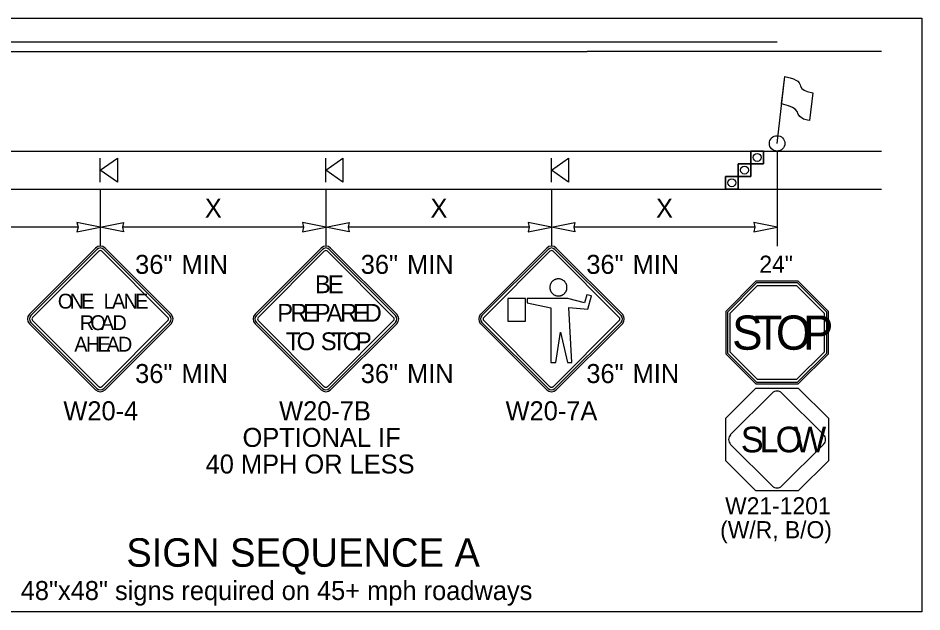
# Model space of a CAD drawing. Extents: x 99999.1 to 100095.7, y 99995 to 100010.7.
# Drawn here: x 100021.344 to 100025.15, y 100006.18 to 100008.68 of the extents above; entities that cross this region are included whole.
import ezdxf

# ---------------------------------------------------------------- set-up
doc = ezdxf.new("R2010")
doc.units = 0
for name, color, linetype in [('RD_ED_ShoulderPavedEdge', 7, 'Continuous'), ('RD_MK_LineDblYellowCenter', 7, 'Continuous'), ('RD_MK_LineEdgeWhite', 7, 'Continuous'), ('RD_MK_LineNoPass', 7, 'Continuous'), ('RD_MK_LineSkipCenter', 7, 'Continuous'), ('SH_DE_DetailHeading2Text', 7, 'Continuous'), ('TR_SN_ConstructionSigns', 7, 'Continuous'), ('TR_WZ_FlaggingStation', 7, 'Continuous'), ('TR_WZ_PortableSignMountBlk-Org', 7, 'Continuous'), ('TR_WZ_TrafficCone', 7, 'Continuous'), ('TR_WZ_WorkZoneDetails', 7, 'Continuous'), ('TR_WZ_WorkZoneTextCurrent', 7, 'Continuous')]:
    doc.layers.add(name, color=color, linetype=linetype)

msp = doc.modelspace()

# ---------------------------------------------------------------- linework, layer by layer
at = {"layer": 'RD_ED_ShoulderPavedEdge'}
msp.add_line((100020.3, 100007.9602), (100024.9804, 100007.9602), dxfattribs=at)
at = {"layer": 'RD_MK_LineDblYellowCenter'}
for p, q in [((100020.3, 100008.5802), (100023.7402, 100008.5802)), ((100020.3, 100008.5402), (100023.7402, 100008.5402))]:
    msp.add_line(p, q, dxfattribs=at)
at = {"layer": 'RD_MK_LineEdgeWhite'}
msp.add_line((100020.3, 100008.1202), (100024.9804, 100008.1202), dxfattribs=at)
at = {"layer": 'RD_MK_LineNoPass'}
msp.add_line((100023.7402, 100008.5802), (100024.5402, 100008.5802), dxfattribs=at)
at = {"layer": 'RD_MK_LineSkipCenter'}
msp.add_lwpolyline([(100024.9804, 100008.5402), (100023.7402, 100008.5402)], dxfattribs=at)
at = {"layer": 'TR_SN_ConstructionSigns'}
for p, q in [((100021.6703, 100007.712), (100021.3919, 100007.4336)), ((100021.6758, 100007.7065), (100021.3974, 100007.428)), ((100021.4051, 100007.4203), (100021.6835, 100007.6987)), ((100021.6968, 100007.6987), (100021.9752, 100007.4203)), ((100021.9829, 100007.428), (100021.7045, 100007.7065)), ((100021.9885, 100007.4336), (100021.71, 100007.712)), ((100022.6203, 100007.712), (100022.3419, 100007.4336)), ((100022.6258, 100007.7065), (100022.3474, 100007.428)), ((100022.3551, 100007.4203), (100022.6335, 100007.6987)), ((100022.6468, 100007.6987), (100022.9252, 100007.4203)), ((100022.9329, 100007.428), (100022.6545, 100007.7065)), ((100022.9385, 100007.4336), (100022.66, 100007.712)), ((100023.5703, 100007.712), (100023.2919, 100007.4336)), ((100023.5758, 100007.7065), (100023.2974, 100007.428)), ((100023.3051, 100007.4203), (100023.5835, 100007.6987)), ((100023.5968, 100007.6987), (100023.8752, 100007.4203)), ((100023.8829, 100007.428), (100023.6045, 100007.7065)), ((100023.8885, 100007.4336), (100023.61, 100007.712)), ((100023.5956, 100007.5735), (100023.5942, 100007.5722)), ((100023.5971, 100007.5747), (100023.5956, 100007.5735)), ((100023.5986, 100007.5759), (100023.5971, 100007.5747)), ((100023.6002, 100007.5769), (100023.5986, 100007.5759)), ((100023.6019, 100007.5779), (100023.6002, 100007.5769)), ((100023.6036, 100007.5788), (100023.6019, 100007.5779)), ((100023.6053, 100007.5796), (100023.6036, 100007.5788)), ((100023.6071, 100007.5803), (100023.6053, 100007.5796)), ((100023.6089, 100007.5809), (100023.6071, 100007.5803)), ((100023.6108, 100007.5814), (100023.6089, 100007.5809)), ((100023.6127, 100007.5818), (100023.6108, 100007.5814)), ((100023.6146, 100007.5821), (100023.6127, 100007.5818)), ((100023.6164, 100007.5823), (100023.6146, 100007.5821)), ((100023.6184, 100007.5824), (100023.6164, 100007.5823)), ((100023.6203, 100007.5824), (100023.6184, 100007.5824)), ((100023.6222, 100007.5823), (100023.6203, 100007.5824)), ((100023.6241, 100007.5821), (100023.6222, 100007.5823)), ((100023.626, 100007.5818), (100023.6241, 100007.5821)), ((100023.6279, 100007.5814), (100023.626, 100007.5818)), ((100023.6297, 100007.5809), (100023.6279, 100007.5814)), ((100023.6316, 100007.5803), (100023.6297, 100007.5809)), ((100023.6333, 100007.5796), (100023.6316, 100007.5803)), ((100023.6351, 100007.5788), (100023.6333, 100007.5796)), ((100023.6368, 100007.5779), (100023.6351, 100007.5788)), ((100023.6385, 100007.5769), (100023.6368, 100007.5779)), ((100023.64, 100007.5759), (100023.6385, 100007.5769)), ((100023.6416, 100007.5747), (100023.64, 100007.5759)), ((100023.643, 100007.5735), (100023.6416, 100007.5747)), ((100023.6445, 100007.5722), (100023.643, 100007.5735)), ((100023.5835, 100007.5502), (100023.5833, 100007.5483)), ((100023.5833, 100007.5483), (100023.5833, 100007.5464)), ((100023.5833, 100007.5464), (100023.5833, 100007.5445)), ((100023.5833, 100007.5445), (100023.5835, 100007.5426)), ((100023.5838, 100007.5522), (100023.5835, 100007.5502)), ((100023.5835, 100007.5426), (100023.5838, 100007.5407)), ((100023.5842, 100007.554), (100023.5838, 100007.5522)), ((100023.5838, 100007.5407), (100023.5842, 100007.5388)), ((100023.5846, 100007.5559), (100023.5842, 100007.554)), ((100023.5842, 100007.5388), (100023.5846, 100007.5369)), ((100023.5852, 100007.5577), (100023.5846, 100007.5559)), ((100023.5846, 100007.5369), (100023.5852, 100007.5351)), ((100023.5858, 100007.5595), (100023.5852, 100007.5577)), ((100023.5852, 100007.5351), (100023.5858, 100007.5333)), ((100023.5865, 100007.5613), (100023.5858, 100007.5595)), ((100023.5873, 100007.563), (100023.5865, 100007.5613)), ((100023.5883, 100007.5647), (100023.5873, 100007.563)), ((100023.5894, 100007.5664), (100023.5883, 100007.5647)), ((100023.5904, 100007.5679), (100023.5894, 100007.5664)), ((100023.5916, 100007.5694), (100023.5904, 100007.5679)), ((100023.5929, 100007.5709), (100023.5916, 100007.5694)), ((100023.5942, 100007.5722), (100023.5929, 100007.5709)), ((100023.6458, 100007.5709), (100023.6445, 100007.5722)), ((100023.647, 100007.5694), (100023.6458, 100007.5709)), ((100023.6482, 100007.5679), (100023.647, 100007.5694)), ((100023.6494, 100007.5664), (100023.6482, 100007.5679)), ((100023.6504, 100007.5647), (100023.6494, 100007.5664)), ((100023.6513, 100007.563), (100023.6504, 100007.5647)), ((100023.6521, 100007.5613), (100023.6513, 100007.563)), ((100023.6529, 100007.5595), (100023.6521, 100007.5613)), ((100023.6535, 100007.5577), (100023.6529, 100007.5595)), ((100023.6529, 100007.5333), (100023.6535, 100007.5351)), ((100023.6541, 100007.5559), (100023.6535, 100007.5577)), ((100023.6535, 100007.5351), (100023.6541, 100007.5369)), ((100023.6545, 100007.554), (100023.6541, 100007.5559)), ((100023.6541, 100007.5369), (100023.6545, 100007.5388)), ((100023.6549, 100007.5522), (100023.6545, 100007.554)), ((100023.6545, 100007.5388), (100023.6549, 100007.5407)), ((100023.6552, 100007.5502), (100023.6549, 100007.5522)), ((100023.6549, 100007.5407), (100023.6552, 100007.5426)), ((100023.6553, 100007.5483), (100023.6552, 100007.5502)), ((100023.6552, 100007.5426), (100023.6553, 100007.5445)), ((100023.6554, 100007.5464), (100023.6553, 100007.5483)), ((100023.6553, 100007.5445), (100023.6554, 100007.5464)), ((100024.4506, 100007.5722), (100024.3241, 100007.4457)), ((100024.4534, 100007.5655), (100024.3308, 100007.4429)), ((100024.3421, 100007.4383), (100024.4581, 100007.5542)), ((100024.6295, 100007.5722), (100024.4506, 100007.5722)), ((100024.6267, 100007.5655), (100024.4534, 100007.5655)), ((100024.4581, 100007.5542), (100024.6221, 100007.5542)), ((100024.6221, 100007.5542), (100024.7381, 100007.4383)), ((100024.7493, 100007.4429), (100024.6267, 100007.5655)), ((100024.7561, 100007.4457), (100024.6295, 100007.5722)), ((100023.4059, 100007.4991), (100023.4059, 100007.4044)), ((100023.4812, 100007.4991), (100023.4059, 100007.4991)), ((100023.4812, 100007.4044), (100023.4812, 100007.4991)), ((100023.6596, 100007.4991), (100023.4882, 100007.4991)), ((100023.4882, 100007.4991), (100023.4882, 100007.481)), ((100023.5858, 100007.5333), (100023.5865, 100007.5315)), ((100023.5865, 100007.5315), (100023.5873, 100007.5298)), ((100023.5873, 100007.5298), (100023.5883, 100007.5281)), ((100023.5883, 100007.5281), (100023.5894, 100007.5265)), ((100023.5894, 100007.5265), (100023.5904, 100007.5249)), ((100023.5904, 100007.5249), (100023.5916, 100007.5234)), ((100023.5916, 100007.5234), (100023.5929, 100007.522)), ((100023.5929, 100007.522), (100023.5942, 100007.5206)), ((100023.5942, 100007.5206), (100023.5956, 100007.5193)), ((100023.5956, 100007.5193), (100023.5971, 100007.5181)), ((100023.5971, 100007.5181), (100023.5986, 100007.5169)), ((100023.5986, 100007.5169), (100023.6002, 100007.5159)), ((100023.6002, 100007.5159), (100023.6019, 100007.5149)), ((100023.6019, 100007.5149), (100023.6036, 100007.514)), ((100023.6036, 100007.514), (100023.6053, 100007.5132)), ((100023.6053, 100007.5132), (100023.6071, 100007.5125)), ((100023.6071, 100007.5125), (100023.6089, 100007.5119)), ((100023.6089, 100007.5119), (100023.6108, 100007.5114)), ((100023.6108, 100007.5114), (100023.6127, 100007.511)), ((100023.6127, 100007.511), (100023.6146, 100007.5107)), ((100023.6146, 100007.5107), (100023.6164, 100007.5105)), ((100023.6164, 100007.5105), (100023.6184, 100007.5104)), ((100023.6184, 100007.5104), (100023.6203, 100007.5104)), ((100023.6203, 100007.5104), (100023.6222, 100007.5105)), ((100023.6222, 100007.5105), (100023.6241, 100007.5107)), ((100023.6241, 100007.5107), (100023.626, 100007.511)), ((100023.626, 100007.511), (100023.6279, 100007.5114)), ((100023.6279, 100007.5114), (100023.6297, 100007.5119)), ((100023.6297, 100007.5119), (100023.6316, 100007.5125)), ((100023.6316, 100007.5125), (100023.6333, 100007.5132)), ((100023.6333, 100007.5132), (100023.6351, 100007.514)), ((100023.6351, 100007.514), (100023.6368, 100007.5149)), ((100023.6368, 100007.5149), (100023.6385, 100007.5159)), ((100023.6385, 100007.5159), (100023.64, 100007.5169)), ((100023.64, 100007.5169), (100023.6416, 100007.5181)), ((100023.6416, 100007.5181), (100023.643, 100007.5193)), ((100023.643, 100007.5193), (100023.6445, 100007.5206)), ((100023.6445, 100007.5206), (100023.6458, 100007.522)), ((100023.6458, 100007.522), (100023.647, 100007.5234)), ((100023.647, 100007.5234), (100023.6482, 100007.5249)), ((100023.6482, 100007.5249), (100023.6494, 100007.5265)), ((100023.6494, 100007.5265), (100023.6504, 100007.5281)), ((100023.6504, 100007.5281), (100023.6513, 100007.5298)), ((100023.6513, 100007.5298), (100023.6521, 100007.5315)), ((100023.6521, 100007.5315), (100023.6529, 100007.5333)), ((100023.7291, 100007.482), (100023.6596, 100007.4991)), ((100023.7388, 100007.5148), (100023.7291, 100007.482)), ((100023.7588, 100007.5112), (100023.7388, 100007.5148)), ((100023.7438, 100007.4544), (100023.7588, 100007.5112)), ((100023.4882, 100007.481), (100023.5877, 100007.4612)), ((100023.5877, 100007.4612), (100023.5877, 100007.2309)), ((100023.6759, 100007.2309), (100023.6628, 100007.4613)), ((100023.6628, 100007.4613), (100023.7438, 100007.4544)), ((100024.3241, 100007.4457), (100024.3241, 100007.2668)), ((100024.3308, 100007.4429), (100024.3308, 100007.2696)), ((100024.3421, 100007.2742), (100024.3421, 100007.4383)), ((100024.7381, 100007.4383), (100024.7381, 100007.2742)), ((100024.7493, 100007.2696), (100024.7493, 100007.4429)), ((100024.7561, 100007.2668), (100024.7561, 100007.4457)), ((100021.3919, 100007.3938), (100021.6703, 100007.1154)), ((100021.3974, 100007.3993), (100021.6758, 100007.1209)), ((100021.6835, 100007.1286), (100021.4051, 100007.4071)), ((100021.9752, 100007.4071), (100021.6968, 100007.1286)), ((100021.7045, 100007.1209), (100021.9829, 100007.3993)), ((100021.71, 100007.1154), (100021.9885, 100007.3938)), ((100022.3419, 100007.3938), (100022.6203, 100007.1154)), ((100022.3474, 100007.3993), (100022.6258, 100007.1209)), ((100022.6335, 100007.1286), (100022.3551, 100007.4071)), ((100022.9252, 100007.4071), (100022.6468, 100007.1286)), ((100022.6545, 100007.1209), (100022.9329, 100007.3993)), ((100022.66, 100007.1154), (100022.9385, 100007.3938)), ((100023.2919, 100007.3938), (100023.5703, 100007.1154)), ((100023.2974, 100007.3993), (100023.5758, 100007.1209)), ((100023.5835, 100007.1286), (100023.3051, 100007.4071)), ((100023.4059, 100007.4044), (100023.4812, 100007.4044)), ((100023.8752, 100007.4071), (100023.5968, 100007.1286)), ((100023.6045, 100007.1209), (100023.8829, 100007.3993)), ((100023.61, 100007.1154), (100023.8885, 100007.3938)), ((100023.6079, 100007.2309), (100023.6276, 100007.3576)), ((100023.6276, 100007.3576), (100023.6579, 100007.2309)), ((100024.3308, 100007.2696), (100024.4534, 100007.147)), ((100024.4581, 100007.1582), (100024.3421, 100007.2742)), ((100024.7381, 100007.2742), (100024.6221, 100007.1582)), ((100024.6267, 100007.147), (100024.7493, 100007.2696)), ((100023.5877, 100007.2309), (100023.6079, 100007.2309)), ((100023.6579, 100007.2309), (100023.6759, 100007.2309)), ((100024.3241, 100007.2668), (100024.4506, 100007.1402)), ((100024.6295, 100007.1402), (100024.7561, 100007.2668)), ((100024.6221, 100007.1582), (100024.4581, 100007.1582)), ((100024.4506, 100007.1402), (100024.6295, 100007.1402)), ((100024.4534, 100007.147), (100024.6267, 100007.147)), ((100024.5197, 100007.1019), (100024.3444, 100006.9266)), ((100024.7357, 100006.9266), (100024.5604, 100007.1019)), ((100024.3444, 100006.8859), (100024.5197, 100006.7106)), ((100024.5604, 100006.7106), (100024.7357, 100006.8859))]:
    msp.add_line(p, q, dxfattribs=at)
msp.add_lwpolyline([(100024.7561, 100006.9957), (100024.7561, 100006.8168), (100024.6295, 100006.6902), (100024.4506, 100006.6902), (100024.3241, 100006.8168), (100024.3241, 100006.9957), (100024.4506, 100007.1222), (100024.6295, 100007.1222)], close=True, dxfattribs=at)
for centre, radius, start, end in [((100021.6902, 100007.6921), 0.0281, 45, 135), ((100021.6902, 100007.6921), 0.0203, 45, 135), ((100021.6902, 100007.6921), 0.00937, 45, 135), ((100022.6402, 100007.6921), 0.0281, 45, 135), ((100022.6402, 100007.6921), 0.0203, 45, 135), ((100022.6402, 100007.6921), 0.00937, 45, 135), ((100023.5902, 100007.6921), 0.0281, 45, 135), ((100023.5902, 100007.6921), 0.0203, 45, 135), ((100023.5902, 100007.6921), 0.00937, 45, 135), ((100021.4117, 100007.4137), 0.0281, 135, 225), ((100021.4117, 100007.4137), 0.0203, 135, 225), ((100021.9686, 100007.4137), 0.0203, 315, 45), ((100021.9686, 100007.4137), 0.0281, 315, 45), ((100022.3617, 100007.4137), 0.0281, 135, 225), ((100022.3617, 100007.4137), 0.0203, 135, 225), ((100022.9186, 100007.4137), 0.0203, 315, 45), ((100022.9186, 100007.4137), 0.0281, 315, 45), ((100023.3117, 100007.4137), 0.0281, 135, 225), ((100023.3117, 100007.4137), 0.0203, 135, 225), ((100023.8686, 100007.4137), 0.0203, 315, 45), ((100023.8686, 100007.4137), 0.0281, 315, 45), ((100021.4117, 100007.4137), 0.00937, 135, 225), ((100021.9686, 100007.4137), 0.00937, 315, 45), ((100022.3617, 100007.4137), 0.00937, 135, 225), ((100022.9186, 100007.4137), 0.00937, 315, 45), ((100023.3117, 100007.4137), 0.00937, 135, 225), ((100023.8686, 100007.4137), 0.00937, 315, 45), ((100021.6902, 100007.1353), 0.0203, 225, 315), ((100021.6902, 100007.1353), 0.00937, 225, 315), ((100022.6402, 100007.1353), 0.0203, 225, 315), ((100022.6402, 100007.1353), 0.00937, 225, 315), ((100023.5902, 100007.1353), 0.0203, 225, 315), ((100023.5902, 100007.1353), 0.00937, 225, 315), ((100021.6902, 100007.1353), 0.0281, 225, 315), ((100022.6402, 100007.1353), 0.0281, 225, 315), ((100023.5902, 100007.1353), 0.0281, 225, 315), ((100024.5401, 100007.0815), 0.0288, 45, 135), ((100024.3648, 100006.9062), 0.0288, 135, 225), ((100024.7153, 100006.9062), 0.0288, 315, 45), ((100024.5401, 100006.731), 0.0288, 225, 315)]:
    msp.add_arc(centre, radius, start, end, dxfattribs=at)
at = {"layer": 'TR_WZ_FlaggingStation'}
for p, q in [((100024.5402, 100008.1527), (100024.5722, 100008.4337)), ((100024.5592, 100008.3196), (100024.5723, 100008.434)), ((100024.6902, 100008.3662), (100024.6769, 100008.249)), ((100024.5592, 100008.3196), (100024.5592, 100008.3196))]:
    msp.add_line(p, q, dxfattribs=at)
for points in [[(100024.5723, 100008.434), (100024.578, 100008.4327), (100024.5958, 100008.4293), (100024.6097, 100008.4251), (100024.6193, 100008.419), (100024.6279, 100008.4143), (100024.6335, 100008.4075), (100024.6378, 100008.3996), (100024.6383, 100008.3934), (100024.6437, 100008.3842), (100024.6545, 100008.3768), (100024.6669, 100008.3716), (100024.6902, 100008.3662)], [(100024.6769, 100008.249), (100024.6687, 100008.2504), (100024.6511, 100008.255), (100024.6354, 100008.2655), (100024.6289, 100008.2761), (100024.625, 100008.2864), (100024.6159, 100008.2973), (100024.6049, 100008.3035), (100024.5876, 100008.3106), (100024.5592, 100008.3196)]]:
    msp.add_lwpolyline(points, dxfattribs=at)
msp.add_circle((100024.5402, 100008.1527), 0.0325, dxfattribs=at)
at = {"layer": 'TR_WZ_PortableSignMountBlk-Org'}
for p, q in [((100021.6902, 100007.9902), (100021.6902, 100008.0902)), ((100022.6402, 100007.9902), (100022.6402, 100008.0902)), ((100023.5902, 100007.9902), (100023.5902, 100008.0902))]:
    msp.add_line(p, q, dxfattribs=at)
for points in [[(100021.6902, 100008.0401), (100021.762, 100008.0902), (100021.762, 100007.9902)], [(100022.6402, 100008.0401), (100022.712, 100008.0902), (100022.712, 100007.9902)], [(100023.5902, 100008.0401), (100023.662, 100008.0902), (100023.662, 100007.9902)]]:
    msp.add_lwpolyline(points, close=True, dxfattribs=at)
at = {"layer": 'TR_WZ_TrafficCone'}
for points in [[(100024.4295, 100008.1202), (100024.4828, 100008.1202), (100024.4828, 100008.0669), (100024.4295, 100008.0669), (100024.4295, 100008.1202)], [(100024.4295, 100008.0669), (100024.4828, 100008.0669), (100024.4828, 100008.1202), (100024.4295, 100008.1202), (100024.4295, 100008.0669)], [(100024.3762, 100008.0669), (100024.4295, 100008.0669), (100024.4295, 100008.0136), (100024.3762, 100008.0136), (100024.3762, 100008.0669)], [(100024.3762, 100008.0136), (100024.4295, 100008.0136), (100024.4295, 100008.0669), (100024.3762, 100008.0669), (100024.3762, 100008.0136)], [(100024.3228, 100008.0136), (100024.3762, 100008.0136), (100024.3762, 100007.9602), (100024.3228, 100007.9602), (100024.3228, 100008.0136)], [(100024.3228, 100007.9602), (100024.3762, 100007.9602), (100024.3762, 100008.0136), (100024.3228, 100008.0136), (100024.3228, 100007.9602)]]:
    msp.add_lwpolyline(points, dxfattribs=at)
for centre in [(100024.4562, 100008.0936), (100024.4028, 100008.0402), (100024.3495, 100007.9869)]:
    msp.add_circle(centre, 0.0167, dxfattribs=at)
at = {"layer": 'TR_WZ_WorkZoneDetails'}
for p, q in [((100024.5402, 100008.1202), (100024.5402, 100007.7202)), ((100021.6902, 100007.9602), (100021.6902, 100007.7202)), ((100022.6402, 100007.9602), (100022.6402, 100007.7202)), ((100023.5902, 100007.9602), (100023.5902, 100007.7202)), ((100021.5964, 100007.8002), (100020.8339, 100007.8002)), ((100022.5464, 100007.8002), (100021.7839, 100007.8002)), ((100023.4964, 100007.8002), (100022.7339, 100007.8002)), ((100024.4464, 100007.8002), (100023.6839, 100007.8002))]:
    msp.add_line(p, q, dxfattribs=at)
for points in [[(100021.6902, 100007.8002), (100021.5919, 100007.8195), (100021.5964, 100007.8002), (100021.5919, 100007.781)], [(100021.6902, 100007.8002), (100021.7884, 100007.8195), (100021.7839, 100007.8002), (100021.7884, 100007.781)], [(100022.6402, 100007.8002), (100022.5419, 100007.8195), (100022.5464, 100007.8002), (100022.5419, 100007.781)], [(100022.6402, 100007.8002), (100022.7384, 100007.8195), (100022.7339, 100007.8002), (100022.7384, 100007.781)], [(100023.5902, 100007.8002), (100023.4919, 100007.8195), (100023.4964, 100007.8002), (100023.4919, 100007.781)], [(100023.5902, 100007.8002), (100023.6884, 100007.8195), (100023.6839, 100007.8002), (100023.6884, 100007.781)], [(100024.5402, 100007.8002), (100024.4419, 100007.8195), (100024.4464, 100007.8002), (100024.4419, 100007.781)]]:
    msp.add_lwpolyline(points, close=True, dxfattribs=at)
at = {"layer": 'TR_WZ_WorkZoneTextCurrent'}
msp.add_lwpolyline([(100020.1, 100008.6802), (100025.15, 100008.6802), (100025.15, 100006.1804), (100020.1, 100006.1804)], close=True, dxfattribs=at)

# ---------------------------------------------------------------- texts
at = {"layer": 'SH_DE_DetailHeading2Text'}
msp.add_text('SIGN SEQUENCE A', height=0.12, rotation=360, dxfattribs=at).set_placement((100021.7998, 100006.3705))
at = {"layer": 'TR_SN_ConstructionSigns'}
for s, height, p in [('36"', 0.08, (100021.8369, 100007.6035)), ('MIN', 0.08, (100022.0319, 100007.6035)), ('36"', 0.08, (100022.7869, 100007.6035)), ('MIN', 0.08, (100022.9819, 100007.6035)), ('36"', 0.08, (100023.7369, 100007.6035)), ('MIN', 0.08, (100023.9319, 100007.6035)), ('36"', 0.08, (100021.8369, 100007.1439)), ('MIN', 0.08, (100022.0319, 100007.1439)), ('36"', 0.08, (100022.7869, 100007.1439)), ('MIN', 0.08, (100022.9819, 100007.1439)), ('36"', 0.08, (100023.7369, 100007.1439)), ('MIN', 0.08, (100023.9319, 100007.1439)), ('W20-4', 0.08, (100021.5347, 100006.9871)), ('W20-7B', 0.08, (100022.4432, 100006.9871)), ('W20-7A', 0.08, (100023.3969, 100006.9871)), ('OPTIONAL IF', 0.08, (100022.2892, 100006.8751)), ('40 MPH OR LESS', 0.08, (100022.1337, 100006.7631)), ('W21-1201', 0.072, (100024.3213, 100006.5913)), ('(W/R, B/O)', 0.072, (100024.3004, 100006.4905))]:
    msp.add_text(s, height=height, rotation=360, dxfattribs=at).set_placement(p)
for s, height, p in [('24"', 0.072, (100024.4654, 100007.6082)), ('B', 0.075, (100022.5939, 100007.5222)), ('E', 0.075, (100022.6482, 100007.5222)), ('O', 0.0625, (100021.5114, 100007.4574)), ('N', 0.0625, (100021.5608, 100007.4574)), ('E', 0.0625, (100021.6095, 100007.4574)), ('L', 0.0625, (100021.7039, 100007.4574)), ('A', 0.0625, (100021.7395, 100007.4574)), ('N', 0.0625, (100021.7883, 100007.4574)), ('E', 0.0625, (100021.837, 100007.4574)), ('P', 0.075, (100022.4353, 100007.4022)), ('R', 0.075, (100022.4905, 100007.4022)), ('E', 0.075, (100022.5437, 100007.4022)), ('P', 0.075, (100022.5932, 100007.4022)), ('A', 0.075, (100022.6431, 100007.4022)), ('R', 0.075, (100022.7004, 100007.4022)), ('E', 0.075, (100022.7536, 100007.4022)), ('D', 0.075, (100022.8031, 100007.4022)), ('R', 0.0625, (100021.6039, 100007.3668)), ('O', 0.0625, (100021.6483, 100007.3668)), ('A', 0.0625, (100021.6927, 100007.3668)), ('D', 0.0625, (100021.7414, 100007.3668)), ('S', 0.144, (100024.3507, 100007.2842)), ('T', 0.144, (100024.4443, 100007.2842)), ('O', 0.144, (100024.535, 100007.2842)), ('P', 0.144, (100024.6488, 100007.2842)), ('T', 0.075, (100022.4719, 100007.2822)), ('O', 0.075, (100022.517, 100007.2822)), ('S', 0.075, (100022.6185, 100007.2822)), ('T', 0.075, (100022.6656, 100007.2822)), ('O', 0.075, (100022.7107, 100007.2822)), ('P', 0.075, (100022.7664, 100007.2822)), ('A', 0.0625, (100021.5808, 100007.2762)), ('H', 0.0625, (100021.6295, 100007.2762)), ('E', 0.0625, (100021.6783, 100007.2762)), ('A', 0.0625, (100021.7158, 100007.2762)), ('D', 0.0625, (100021.7645, 100007.2762)), ('S', 0.108, (100024.3873, 100006.8522)), ('L', 0.108, (100024.4661, 100006.8522)), ('O', 0.108, (100024.5341, 100006.8522)), ('W', 0.108, (100024.6108, 100006.8522))]:
    msp.add_text(s, height=height, dxfattribs=at).set_placement(p)
at = {"layer": 'TR_WZ_WorkZoneTextCurrent'}
for p in [(100022.1304, 100007.8402), (100023.0804, 100007.8402), (100024.0304, 100007.8402)]:
    msp.add_text('X', height=0.08, rotation=360, dxfattribs=at).set_placement(p)
msp.add_text('48"x48" signs required on 45+ mph roadways', height=0.08, dxfattribs=at).set_placement((100021.3551, 100006.2305))

doc.saveas('drawing.dxf')
